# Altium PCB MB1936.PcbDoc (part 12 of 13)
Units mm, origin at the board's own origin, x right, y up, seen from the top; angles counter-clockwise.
Board outline 172 x 137 mm, 6 copper layers (Top Layer, Signal Layer 1, Signal Layer 2, Signal Layer 3, Signal Layer 4, Bottom Layer), stack 1.549 mm thick; 859 components, 672 nets, 3477 pads, 2222 vias.
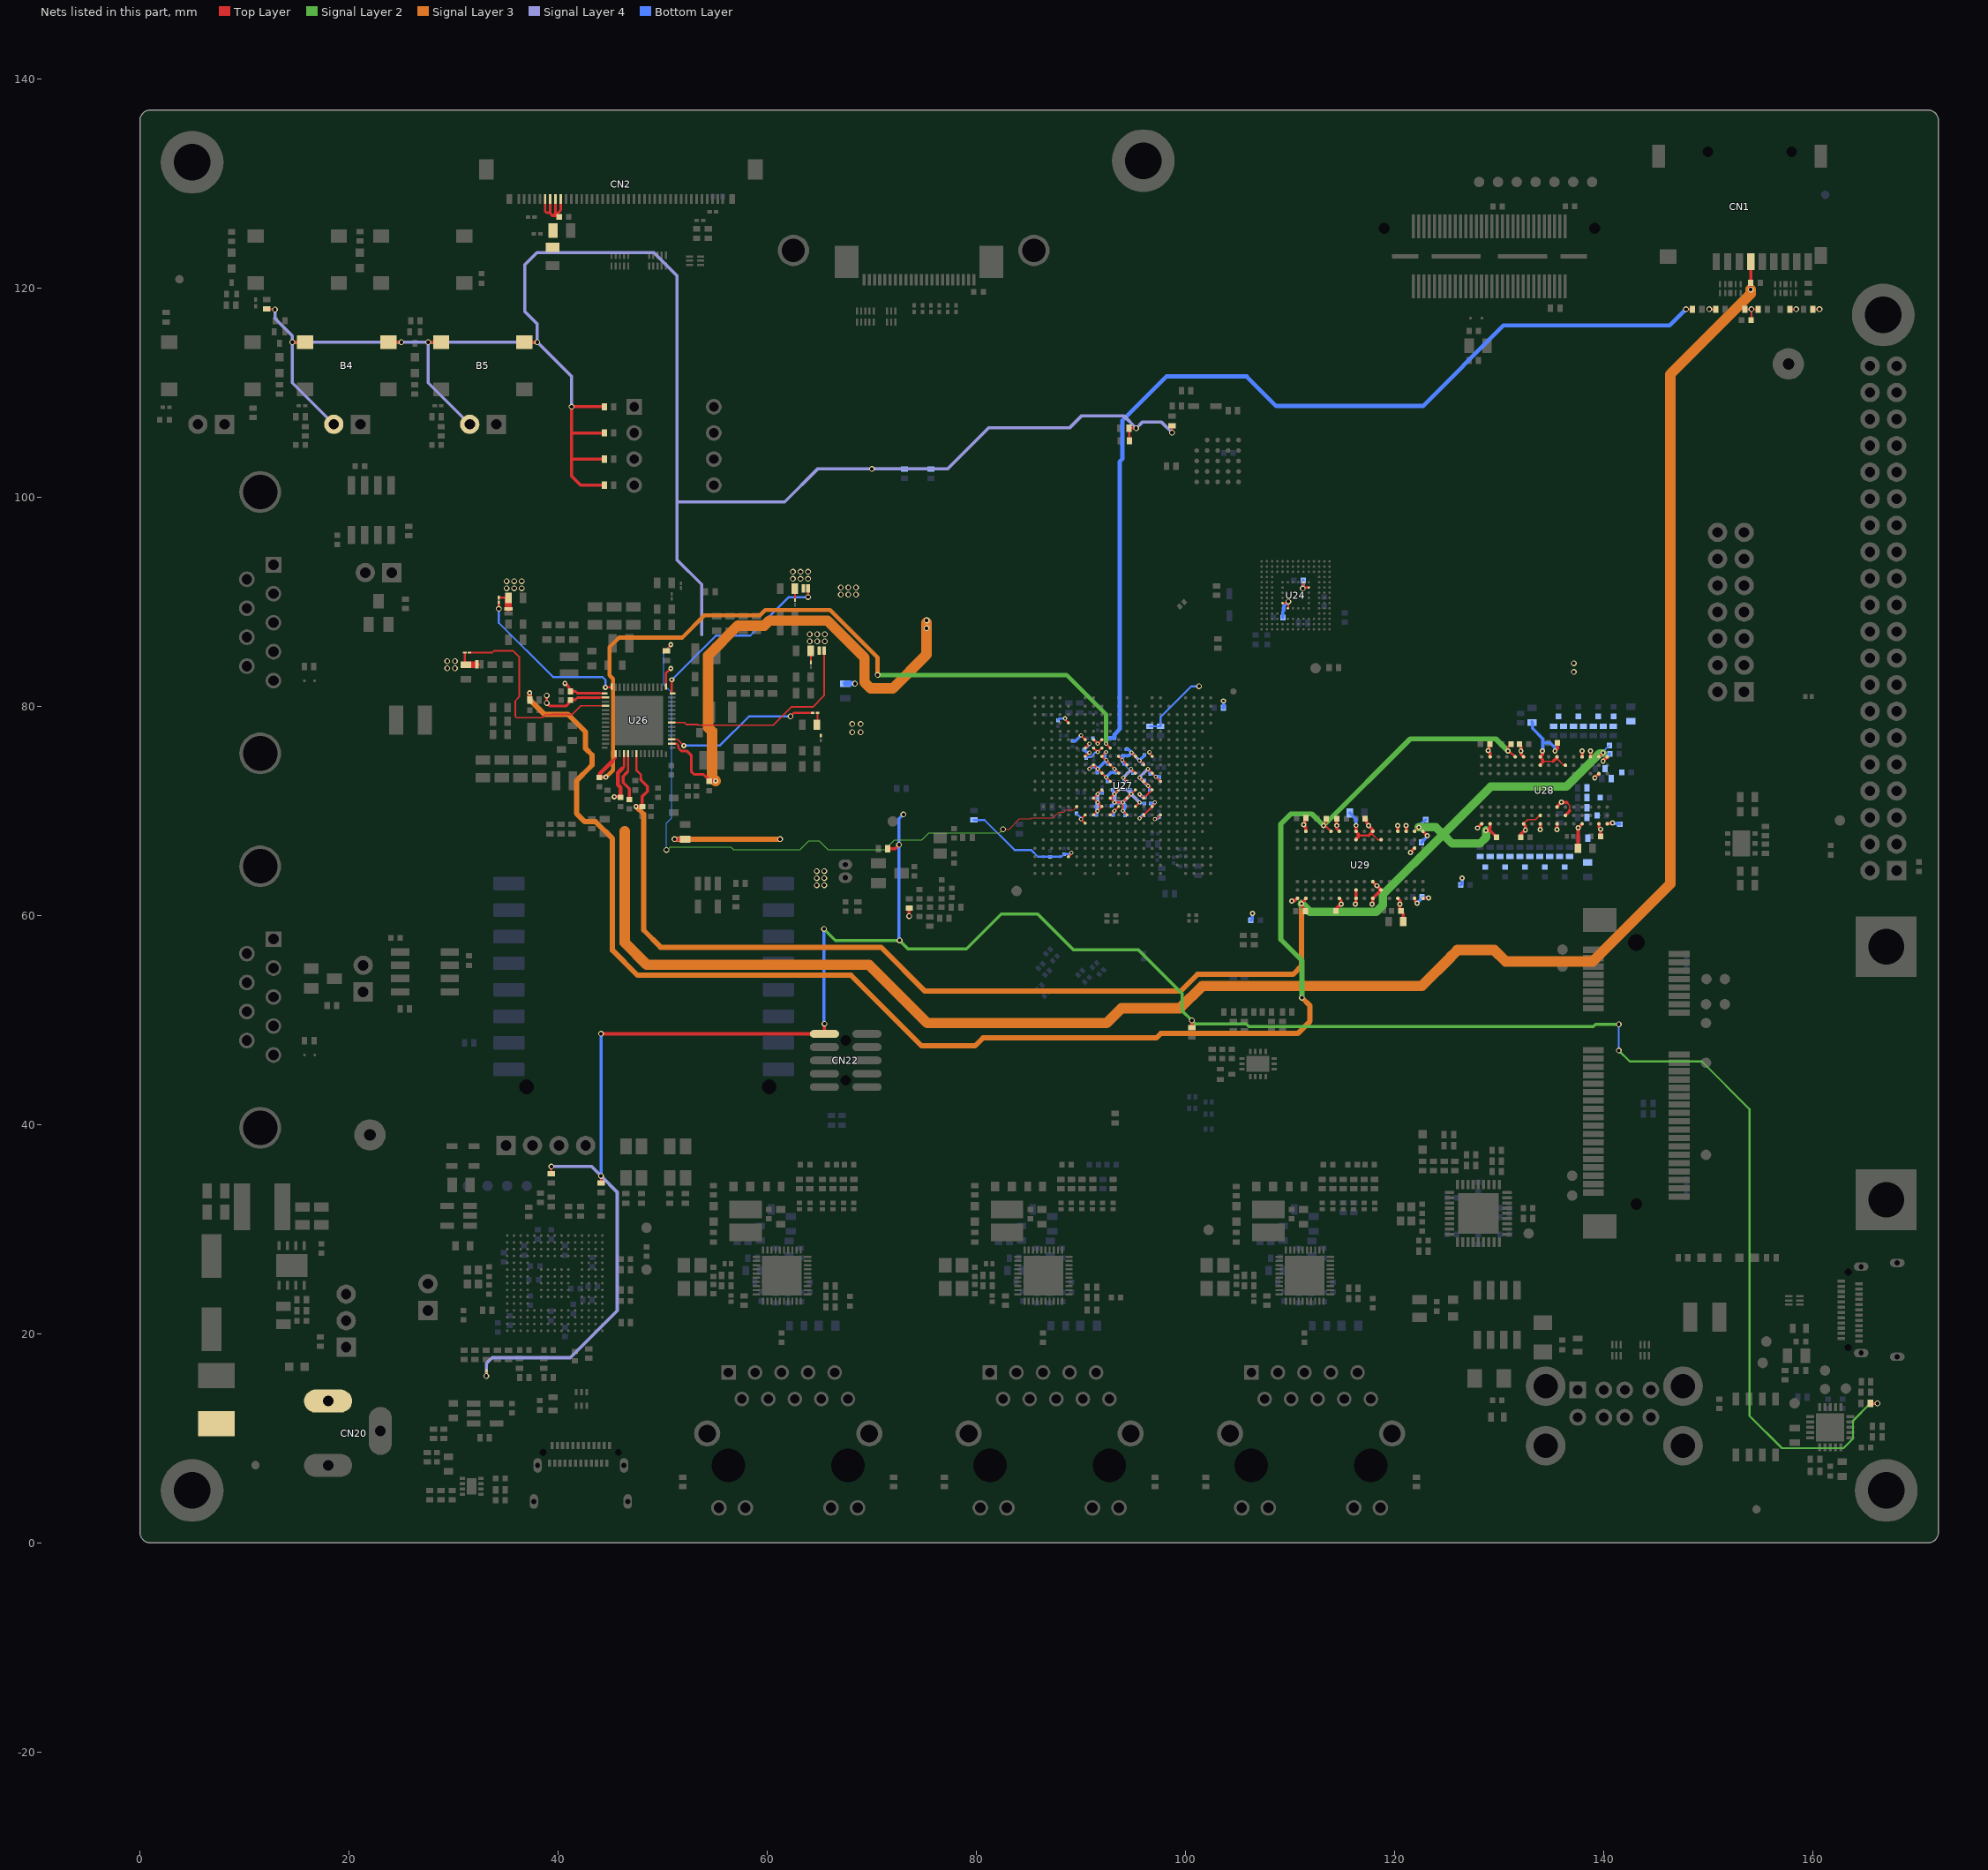
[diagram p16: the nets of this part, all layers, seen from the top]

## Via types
v1: diameter 0.55, hole 0.35, Top Layer to Bottom Layer, 1661 vias
v2: diameter 0.4, hole 0.2, Top Layer to Bottom Layer, tented both sides, 253 vias
v3: diameter 0.5, hole 0.2, Top Layer to Bottom Layer, 157 vias
v4: diameter 0.5, hole 0.25, Top Layer to Bottom Layer, 145 vias
v5: diameter 0.4, hole 0.2, Top Layer to Bottom Layer, 6 vias

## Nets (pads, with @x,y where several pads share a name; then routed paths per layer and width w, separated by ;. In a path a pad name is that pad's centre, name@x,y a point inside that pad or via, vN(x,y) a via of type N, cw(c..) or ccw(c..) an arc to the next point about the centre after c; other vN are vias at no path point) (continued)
VDD_DDR: C39.2 C48.2 C50.2 C51.2 C77.2 C79.2 C80.2 C82.2 C84.2 C85.2 C93.2 C94.2 C99.2 C188.2 C189.2 C202.2 C216.2 C217.2 C218.2 C224.2 C227.2 C230.1 C236.2 C237.2 C238.2 C243.2 C247.2 C261.2 C262.2 C264.2 LNK8.2 LNK9.2 R47.2 U26.43 U27.K15 U27.L14 U27.L16 U27.M15 U27.N14 U27.P15 U27.R14 U27.R16 U28.A1 U28.A9 U28.B3 U28.B9 U28.C1 U28.D1 U28.D9 U28.F2 U28.F8 U28.G1 U28.G7 U28.G9 U28.J1 U28.J2 U28.J8 U28.J9 U28.L1 U28.L9 U28.R1 U28.T9 U29.A1 U29.A9 U29.B3 U29.B9 U29.C1 U29.D1 U29.D9 U29.F2 U29.F8 U29.G1 U29.G7 U29.G9 U29.J1 U29.J2 U29.J8 U29.J9 U29.L1 U29.L9 U29.R1 U29.T9 | length 77.5
  Top Layer w0.09: U29.J8@116.269,62.399 U29.J8@116.269,62.424 ; 135.525,74.975 U28.G1@135.525,75.094
  Top Layer w0.1: U27.R16@97.575,69.6 U27.R16@97.6,69.6
  Top Layer w0.15: 117.718,67.815 117.757,67.815 117.797,67.775 117.845,67.775 118.389,67.232 118.694,67.232 U29.F2@118.7,67.225 ; U29.G1@117.9,67.998 U29.G1@117.9,68.025 ; U28.L9@132.325,68.75 132.325,68.775 132.7,69.15 133.475,69.15 U28.J8@133.936,69.611 ; 134.158,74.728 135.167,74.728 ; 135.525,74.975 136.15,74.35 U28.F2@136.325,74.35 ; 136.45,70.8 136.725,70.525 136.725,70.05
  Top Layer w0.2: LNK8.2@31.075,85.125 31.075,84.077 R47.2@31.175,83.977 ; v2(95.6,69.275) 95.675,69.275 U27.P15@96.8,70.4 97.05,70.65 v2(97.05,70.8) ; v2(95.6,73.15) 95.65,73.15 U27.L14@96,72.8 v2(96.42,72.379) ; v2@95.625,71.575 U27.N14@96,71.2 U27.M15@96.8,72 v2@96.421,72.379 ; v2(96.4,74) U27.K15@96.8,73.6 v2(97.15,73.25) ; v2(97.05,69.2) 97.2,69.2 U27.R16@97.6,69.6 ; v2@97.125,73.275 v2(97.15,73.25) ; U27.L16@97.6,72.8 v2(97.15,73.25) ; 116.526,67.625 117.535,67.625 ; U29.B9@121.9,61.625 121.906,61.619 121.906,61.394 v4(122.15,61.15) ; U29.A9@122.7,61.625 122.725,61.65 123.225,61.65 v4(123.25,61.675)
  Top Layer w0.21: 43.975,81.227 U26.43@44.53,81.227
  Top Layer w0.25: 40.895,81.952 40.899,81.952 41.045,81.806 41.045,81.512 C39.2@41.155,81.402 ; C39.2@41.205,81.402 41.675,81.402 41.85,81.227 43.975,81.227
  Top Layer w0.3: v3@40.644,82.203 40.895,81.952 ; v4@110.105,61.41 v4(110.144,61.372) 110.182,61.41 110.459,61.41 110.673,61.625 U29.T9@110.7,61.625 ; U29.R1@111.5,68.025 111.481,68.044 111.481,68.415 111.3,68.596 v4(111.3,68.65) 111.3,68.704 111.42,68.824 111.42,69.195 C77.2@111.525,69.3 ; C94.2@114.356,60.385 C94.2@114.394,60.422 ; C79.2@114.45,69.197 v4(114.45,68.6) 114.45,68.3 114.7,68.05 U29.L1@114.7,68.025 ; C94.2@114.468,60.697 114.846,61.075 v4(114.9,61.075) 114.862,61.113 114.862,61.436 114.7,61.598 U29.L9@114.7,61.625 ; v4(116.25,61.075) 116.3,61.125 U29.J9@116.3,61.625 U29.J8@116.3,62.425 ; U29.J2@116.3,67.225 116.32,67.244 116.32,67.317 116.526,67.524 116.526,67.625 116.526,67.772 116.3,67.998 U29.J1@116.3,68.025 v4(116.3,68.6) ; C80.2@117.325,69.25 117.325,68.857 117.4,68.782 117.4,68.729 117.5,68.629 v4(117.5,68.575) 117.5,68.55 117.881,68.169 117.881,68.044 U29.G1@117.9,68.025 ; 117.535,67.625 117.535,67.632 117.718,67.815 U29.G1@117.9,67.998 ; v4@117.896,61.08 117.9,61.084 U29.G9@117.9,61.625 U29.F8@118.7,62.425 118.688,62.425 118.3,62.813 v4(118.3,62.825) 117.913,63.213 117.9,63.213 U29.G7@117.9,63.225 ; U29.D9@120.3,61.625 120.5,61.425 v4(120.5,61.075) 120.47,61.045 120.47,60.53 120.575,60.425 120.825,60.175 C99.2@120.825,59.4 ; U29.D1@120.3,68.025 v4(120.3,68.575) ; U29.C1@121.1,68.025 v4(121.1,68.575) ; v4(121.5,66.025) U29.B3@121.9,66.425 ; U29.A1@122.7,68.025 v4(123.1,67.625) ; v4(127.927,68.35) 128.305,68.728 U28.T9@128.332,68.728 ; C51.2@129.052,76.298 129.052,75.927 128.932,75.807 128.932,75.699 129.113,75.518 U28.R1@129.113,75.147 ; C50.2@131.925,76.325 131.925,76.3 132.082,76.143 132.082,75.703 132.082,75.403 132.332,75.153 U28.L1@132.332,75.128 ; C84.2@132.025,67.425 C84.2@132.05,67.45 132.1,67.499 132.1,67.8 132.478,68.178 132.497,68.178 v4@132.5,68.175 ; U28.L9@132.332,68.701 132.5,68.533 v4@132.5,68.175 ; v4(132.5,68.15) v4@132.5,68.175 ; v4(133.9,68.2) 133.925,68.225 U28.J9@133.925,68.75 ; U28.J1@133.925,75.15 134.125,75.35 v4(134.125,75.7) ; U28.J2@133.932,74.328 133.951,74.347 133.951,74.42 134.158,74.627 134.158,74.728 134.158,74.875 U28.J1@133.932,75.101 ; 135.167,74.728 135.167,74.735 U28.G1@135.525,75.094 ; v4(135.325,75.7) 135.575,75.95 C48.2@135.575,76.375 ; v4(135.5,68.2) 135.525,68.225 U28.G9@135.525,68.75 ; U28.G7@135.525,70.35 135.525,70.4 v4(135.925,70.8) 136.45,70.8 ; U28.F8@136.325,69.55 136.725,69.95 136.725,70.05 ; C85.2@137.525,66.425 137.542,66.442 137.542,68.367 v4(137.55,68.375) 137.903,68.728 U28.D9@137.932,68.728 ; U28.D1@137.932,75.128 v4@137.932,75.678 ; U28.C1@138.732,75.128 v4@138.732,75.678 ; v4(139.125,73.15) U28.B3@139.525,73.55 ; U28.B9@139.525,68.75 139.535,68.74 139.535,68.445 139.7,68.279 v4(139.7,68.225) 139.688,68.213 139.688,67.563 C82.2@139.675,67.55 ; v4(139.925,74.75) U28.A1@140.325,75.15 ; U28.A9@140.325,68.75 140.335,68.76 140.73,68.76 140.796,68.825 v4(140.85,68.825)
  Top Layer w0.64: R47.2@31.175,83.977 LNK9.2@32.173,83.977
  Signal Layer 4 w0.3: v2(95.6,73.15) 96.356,72.394 96.406,72.394 v2@96.425,72.375 ; v2@95.716,73.179 95.716,73.316 v2(96.4,74)
  Bottom Layer w0.09: C202.2@140.55,75.425 C202.2@140.575,75.4
  Bottom Layer w0.2: v2(96.4,74) 96.4,73.946 96.549,73.796 96.549,73.599 C216.2@96.624,73.524 ; C216.2@96.631,73.524 96.704,73.452 96.933,73.452 97.135,73.25 v2(97.15,73.25) ; v2@97.125,73.275 v2(97.15,73.25) ; v2@97.15,73.23 v2(97.15,73.25)
  Bottom Layer w0.3: v2@95.6,69.229 v2(95.6,69.275) 95.875,69.55 95.95,69.55 C243.2@95.975,69.575 ; v2(95.6,71.575) 95.9,71.275 C227.2@96.1,71.275 ; v2(95.6,73.15) 95.627,73.15 95.863,72.914 96.035,72.914 96.074,72.874 96.099,72.85 96.099,72.7 v2(96.42,72.379) ; v2@96.425,72.375 96.425,72.347 96.549,72.223 96.549,71.999 C224.2@96.574,71.974 ; C230.1@96.675,70.7 96.7,70.725 96.948,70.725 97.023,70.8 v2(97.05,70.8) ; v2(97.05,69.2) 97.069,69.219 97.269,69.219 C237.2@97.45,69.4 ; v2@97.125,73.275 97.425,73.275 C217.2@97.5,73.2 ; C189.2@103.62,79.846 103.625,79.851 v4(103.625,80.5) ; C264.2@106.25,59.525 106.4,59.675 v4(106.4,60.175) ; C236.2@115.7,69.8 116.088,69.412 ; 116.125,69.375 116.3,69.2 v4(116.3,68.6) ; v4@122.075,61.1 122.65,61.675 v4(123.25,61.675) ; C247.2@122.575,66.975 123.1,67.5 v4(123.1,67.625) ; C261.2@126.3,62.9 126.45,63.05 v4(126.45,63.55) ; C188.2@133.125,78.5 C188.2@133.125,78.425 133.166,78.384 133.166,77.873 134.166,76.873 134.166,76.487 ; v4(134.125,75.7) 134.166,75.741 134.166,76.487 ; v4(135.325,75.7) 135.325,76.025 134.864,76.487 134.166,76.487 ; v4(139.925,74.75) 139.925,74.8 140.55,75.425 C202.2@140.438,75.313 ; v4@140.875,68.775 141.475,68.775 C238.2@141.525,68.725
  other v1: 29.4,83.625 30.125,83.625 29.4,84.3 30.125,84.3
  other v3: 40.65,82.175
  other v4: 117.85,61.075 137.925,75.7 138.725,75.7 132.075,75.725 128.925,75.75
VDD_DDR_FB: LNK8.1 U26.46 | length 20.1
  Top Layer w0.15: LNK8.1@31.525,85.125 33.7,85.125 33.875,85.3 35.687,85.3 35.871,85.116 36.275,84.712 36.275,80.875 35.9,80.5 35.9,79.017 36.017,78.9 38.467,78.9 38.767,79.2 39.437,79.2 39.439,79.202 41.327,79.202 42.152,80.027 U26.46@44.53,80.027
VDD_EMMC: C65.1 C177.2 C180.2 U24.E6 U24.F5 U24.J10 U24.K9 U26.16 | length 54.6
  Top Layer w0.2: U24.E6@109.275,89.85 109.58,89.85 109.73,90 v1(109.825,90) ; U24.F5@109.775,89.35 109.775,89.358 109.825,89.408 v1@109.825,89.85 ; v1(111.2,91.25) v1@111.275,91.325 ; U24.J10@111.275,91.85 111.275,91.42 111.267,91.412 111.267,91.333 v1@111.275,91.325 ; U24.K9@111.775,91.35 111.395,91.35 111.362,91.317 111.283,91.317 v1@111.275,91.325
  Top Layer w0.21: U26.16@50.87,76.427 51.3,76.427 51.488,76.24 51.488,76.015 51.634,75.868
  Top Layer w0.25: 51.632,75.865 51.798,75.699 52.328,75.699 52.725,75.302 52.725,73.752 53,73.477 53.895,73.477 54.45,72.922 C65.1@54.45,72.852
  Top Layer w0.3: C65.1@54.45,72.852 v3(55.06,72.852)
  Signal Layer 3 w1: v3(55.06,72.852) 54.705,73.207 54.705,77.595 54.35,77.95 54.35,84.85 57.206,87.706 59.719,87.706 60.188,88.175 65.75,88.175 69.3,84.625 69.3,82.286 69.886,81.7 72,81.7 75.225,84.925 v1(75.225,87.45) v1@75.225,88
  Bottom Layer w0.3: C180.2@109.3,88.475 109.3,89.049 109.4,89.149 109.4,89.575 v1(109.825,90) ; v1(111.2,91.25) 111.225,91.275 111.225,92 C177.2@111.25,92.025
  other v1: 75.225,88.2
VDD_SDCARD: C6.2 C72.1 CN1.4 U26.4 | length 188
  Top Layer w0.21: 46.125,74.027 46.3,74.202 U26.4@46.3,75.457
  Top Layer w0.3: v3(45.365,71.337) C72.1@45.975,71.337 ; v1(154.05,119.83) C6.2@154.05,120.48 CN1.4@154.05,122.5
  Top Layer w0.4: C72.1@45.975,71.337 45.975,72.22 45.71,72.485 45.71,73.612 46.125,74.027
  Signal Layer 3 w1: 46.375,68.025 46.375,57.375 48.475,55.275 69.725,55.275 75.3,49.7 92.45,49.7 93.875,51.125 99.475,51.125 101.6,53.25 122.6,53.25 125.4,56.05 125.4,56.089 125.986,56.675 129.525,56.675 130.6,55.6 138.95,55.6 146.35,63 146.35,111.725 154.05,119.425 v1(154.05,119.83)
VDD_XXXX: C73.1 U26.5 | length 4.6
  Top Layer w0.21: 46.578,73.655 46.7,73.777 U26.5@46.7,75.457
  Top Layer w0.3: 46.578,73.655 46.21,73.287 46.21,72.692 46.8,72.102 46.8,71.337
VDDA1V8_AON: C234.2 R58.2 R70.1 U27.R7 U27.T7 | length 13.7
  Top Layer w0.2: v2(90,69.2) U27.R7@90.4,69.6 ; v2(90,69.2) U27.T7@90.4,68.8
  Top Layer w0.3: v1(51.125,67.275) R58.2@52.15,67.275 ; v1(73.575,59.925) R70.1@73.575,60.675
  Signal Layer 3 w0.5: v1(51.125,67.275) v1(61.225,67.275)
  Bottom Layer w0.2: C234.2@89.575,69.7 89.625,69.7 89.962,69.364 89.962,69.238 v2(90,69.2)
VDDCORE: C192.2 C197.2 C201.2 C204.1 C207.2 C210.2 C213.2 C214.2 C219.1 LNK2.2 LNK5.1 R36.2 R249.1 U27.D5 U27.F7 U27.G7 U27.H7 U27.H9 U27.J8 U27.J10 U27.K9 U27.K11 U27.L10 | length 18.9
  Top Layer w0.2: LNK5.1@62.65,90.15 62.65,91.232 R36.2@62.63,91.252 R36.2@62.653,91.275 ; v2(88.475,78.825) 88.475,78.725 U27.D5@88.8,78.4 ; v2(90,77.2) U27.F7@90.4,76.8 U27.F7@90.425,76.8 ; U27.H7@90.4,75.2 90.425,75.2 90.775,75.55 v2(90.8,75.55) ; U27.G7@90.4,76 v2(90.8,76.4) ; v2(90.8,74) U27.J8@91.2,74.4 v2(91.6,74) v2(92.4,73.2) U27.L10@92.8,72.8 ; v2(92.4,75.6) U27.H9@92,75.2 v2@92.425,74.775 ; v2(92.425,74.85) v2@92.425,74.775 ; U27.K11@93.6,73.6 v2(93.2,74) U27.J10@92.8,74.4 v2@92.425,74.775
  Bottom Layer w0.2: C192.2@87.8,78.7 87.9,78.8 88.038,78.8 v2@88.4,78.8
  Bottom Layer w0.3: C197.2@89.2,76.675 89.475,76.675 v2(90,77.2) ; v2(90.8,74) 91,74.2 91.4,74.2 v2(91.6,74) ; v2(90.8,75.55) 90.576,75.55 C201.2@90.3,75.825 90.8,76.325 v2(90.8,76.4) ; C214.2@91.55,73.65 91.55,73.95 v2(91.6,74) ; v2(92.4,75.6) 92.275,75.475 C204.1@92.275,75.25 92.275,75 v2(92.425,74.85) ; C219.1@92.55,72.825 92.55,73.05 v2(92.4,73.2) 92.85,73.65 C213.2@93.326,73.65 93.325,73.875 v2(93.2,74) ; C210.2@92.551,74.475 92.55,74.725 v2(92.425,74.85) ; v2(91.6,74) 92.425,74.825 v2(92.425,74.85)
  Bottom Layer w0.5: R249.1@67.45,82.15 v1(68.375,82.15)
  other v1: 62.45,92.175 63.175,92.175 63.9,92.175 62.45,92.85 63.175,92.85 63.9,92.85
VDDCORE_FB: LNK2.1 U26.28 | length 18.5
  Top Layer w0.2: U26.28@50.87,81.227 v3(50.87,82.527) ; v1(63.9,90.425) LNK2.1@63.9,91.275
  Bottom Layer w0.2: v3(50.87,82.527) 55.093,86.75 58.375,86.75 62.05,90.425 v1(63.9,90.425)
VDDCPU: C199.2 C200.1 C203.2 C208.2 C209.2 C215.1 C220.2 LNK4.1 LNK6.1 R39.2 U27.H11 U27.H13 U27.H15 U27.J12 U27.J14 U27.K13 U27.L12 | length 13.4
  Top Layer w0.2: LNK4.1@34.325,90.375 35.222,90.375 R39.2@35.245,90.352 ; U27.H11@93.6,75.2 v2(93.945,74.855) U27.J12@94.4,74.4 ; v2(94.045,73.155) U27.L12@94.4,72.8 ; v2(94.775,74.005) 95.18,73.6 U27.K13@95.2,73.6 ; v2(94.845,75.555) U27.H13@95.2,75.2 ; v2(95.595,74.805) U27.J14@96,74.4 ; v2(96.54,75.591) 96.578,75.553 96.578,75.449 96.8,75.227 U27.H15@96.8,75.2
  Top Layer w0.64: LNK6.1@35.225,89.354 R39.2@35.225,90.352
  Signal Layer 4 w0.3: v2(94.045,73.155) 94.756,73.866 94.756,73.986 v2(94.775,74.005) ; v2(94.845,75.555) v2(95.595,74.805)
  Bottom Layer w0.1: C208.2@94.15,74.48 94.15,74.379 94.524,74.005 v2(94.775,74.005)
  Bottom Layer w0.2: v2(94.045,73.155) 94.045,72.855 C220.2@94.125,72.775 ; v2@94.775,73.978 v2(94.775,74.005) ; C215.1@94.95,73.625 94.95,73.803 ; v2(95.595,74.805) 95.633,74.767 95.633,74.692 C209.2@95.875,74.45
  Bottom Layer w0.3: C208.2@94.15,74.48 93.945,74.685 v2(93.945,74.855) 93.945,75.17 C203.2@94.025,75.25 94.548,75.25 v2@94.853,75.555 ; C199.2@94.325,75.875 94.525,75.875 v2(94.845,75.555) ; v2@94.775,73.978 94.95,73.803 ; v2(95.595,74.805) C200.1@96.095,75.305
  other v1: 67.025,90.666 67.75,90.666 68.475,90.666 35.065,91.273 35.79,91.273 36.515,91.273 67.025,91.341 67.75,91.341 68.475,91.341 35.065,91.948 35.79,91.948 36.515,91.948
VDDCPU_FB: LNK4.2 U26.42 | length 15.7
  Top Layer w0.2: v1(34.325,89.3) LNK4.2@34.325,89.925 ; v3(44.525,81.802) U26.42@45.095,81.802
  Bottom Layer w0.2: v1(34.325,89.3) 34.325,87.975 39.51,82.79 44.235,82.79 44.525,82.5 v3(44.525,81.802)
VDDGPU: C222.2 C223.2 C229.1 C231.2 C232.2 C242.2 LNK7.2 LNK10.1 R45.2 U27.M11 U27.M13 U27.N10 U27.N12 U27.P13 U27.R12 | length 19.9
  Top Layer w0.2: LNK10.1@64.175,84.175 R45.2@64.175,85.257 ; U27.M11@93.6,72 v2(93.2,71.6) U27.N10@92.8,71.2 v2(93.195,70.805) 93.197,70.803 93.997,70.803 v2(94,70.8) ; U27.R12@94.4,69.6 v2(94,70) v2(94,70.8) ; U27.P13@95.2,70.4 v2(95.6,70.8) ; U27.M13@95.2,72 v2(94.8,71.6) v2(94,70.8)
  Signal Layer 4 w0.2: v2(94,70) v2(94,70.8)
  Signal Layer 4 w0.3: v2(93.2,71.6) 93.675,72.075 94.325,72.075 v2(94.8,71.6) ; v2(94,70.8) v2(94.8,71.6) ; v2(95.6,70.8) v2(94.8,71.6)
  Signal Layer 4 w0.4: v2(93.2,71.6) 93.2,70.8 v2(94,70.8)
  Bottom Layer w0.2: C223.2@93.025,72 93.025,71.775 v2(93.2,71.6) 93.197,71.598 93.197,70.808 v2(93.195,70.805) 93.197,70.803 93.997,70.803 v2(94,70.8) ; v2(95.6,70.8) 95.695,70.705 C229.1@96.075,70.705
  Bottom Layer w0.3: C231.2@92.95,70.48 93.176,70.706 93.176,70.786 v2(93.195,70.805) ; v2(94,70.8) 94.175,70.625 C232.2@94.175,70.425 94.175,70.175 v2(94,70) 94.2,69.8 C242.2@94.2,69.575 ; C222.2@94.675,72 94.8,71.875 v2(94.8,71.6) v2(95.6,70.8)
  other v1: 64.725,62.875 65.45,62.875 64.725,63.55 65.45,63.55 64.725,64.225 65.45,64.225 64.05,86.2 64.775,86.2 65.5,86.2 64.05,86.875 64.775,86.875 65.5,86.875
VDDGPU_FB: LNK7.1 U26.21 | length 20.2
  Top Layer w0.15: U26.21@50.75,78.427 52.083,78.427 52.26,78.25 53.34,78.25 53.413,78.177 60.552,78.177 62.3,79.925 64.35,79.925 65.425,81 LNK7.1@65.425,85.3
VDDIO: B4.1 B4.2 B5.1 B5.2 C196.2 C205.2 C221.2 C228.2 C233.1 C240.2 C241.1 CN7.2 CN8.2 CN22.1 LNK11.2 LNK12.2 LNK13.1 R7.2 R27.2 R31.2 R32.2 R53.2 R67.2 R68.2 R71.2 R76.2 R79.2 R91.2 R107.2 R125.2 R223.2 R245.2 R246.2 R260.2 R261.2 U26.29 U27.F8 U27.F9 U27.G8 U27.G9 U27.M9 U27.N8 U27.P9 U27.P11 U27.R8 U27.R10 | length 464.8
  Top Layer w0.2: R7.2@12.123,117.975 12.148,117.95 12.893,117.95 v1(12.918,117.925) ; v1(33.125,15.95) LNK13.1@33.125,16.43 ; R107.2@39.35,35.3 v1(39.35,35.975) ; R125.2@44.1,34.4 v1(44.1,35.075) ; U26.29@50.3,81.872 50.3,83.125 v3(50.775,83.6) ; R53.2@64.755,78.227 64.8,78.272 LNK11.2@64.8,79.375 ; U27.R8@91.2,69.6 v2(91.575,69.975) U27.P9@92,70.4 v2(91.6,70.8) U27.N8@91.2,71.2 v2(91.6,71.6) U27.M9@92,72 ; U27.G8@91.2,76 91.599,75.6 U27.G9@92,76 ; U27.F8@91.2,76.8 v2(91.6,76.4) U27.F9@92,76.8 ; U27.R10@92.8,69.6 v2(93.2,70) U27.P11@93.6,70.4 ; R32.2@94.63,105.375 94.605,105.4 R31.2@94.605,106.575 v1(95.28,106.575) ; v1(98.709,106.15) R27.2@98.709,106.825 ; R223.2@165.495,13.325 v1(166.17,13.325)
  Top Layer w0.3: v1(14.567,114.8) B4.1@15.812,114.8 ; B4.2@23.763,114.8 v1(25.007,114.8) ; v1(27.568,114.8) B5.1@28.813,114.8 ; B5.2@36.763,114.8 v1(38.008,114.8) ; v1@44.1,48.665 CN22.1@65.465,48.665 65.475,48.675 v1(65.475,49.625) ; R79.2@44.425,101.125 42.15,101.125 41.275,102 41.275,103.575 ; R76.2@44.425,103.625 41.325,103.625 41.275,103.575 ; R71.2@44.425,106.125 41.3,106.125 41.275,106.1 ; R68.2@44.425,108.625 v1(41.275,108.625) 41.275,106.1 ; R67.2@71.525,66.375 72.225,66.375 v1(72.6,66.75) ; R91.2@100.6,49.275 v1(100.6,49.95) ; 41.275,103.575 41.275,106.1
  Signal Layer 2 w0.2: v1(141.425,47.075) 142.475,46.025 149.375,46.025 153.925,41.475 153.925,12.154 157.029,9.05 162.92,9.05 163.825,9.955 163.825,11.672 165.478,13.325 v1(166.17,13.325)
  Signal Layer 2 w0.3: v1(65.425,58.7) 66.525,57.6 v1(72.65,57.6) 73.45,56.8 79.05,56.8 82.375,60.125 85.85,60.125 89.288,56.687 95.489,56.687 99.656,52.52 99.656,50.894 v1(100.6,49.95) 100.925,49.625 105.8,49.625 106.05,49.375 139,49.375 139.2,49.575 v1(141.425,49.575)
  Signal Layer 4 w0.3: v1(12.918,117.925) 12.918,117.057 14.567,115.408 v1(14.567,114.8) ; CN7.2@18.543,106.95 14.567,110.925 v1(14.567,114.8) ; CN8.2@31.543,106.95 27.568,110.925 v1(27.568,114.8) ; v1(33.125,15.95) 33.125,17.15 33.675,17.7 41.15,17.7 45.65,22.2 45.65,33.525 v1(44.1,35.075) 43.2,35.975 v1(39.35,35.975) ; v1(41.275,108.625) 41.275,111.533 v1(38.008,114.8) ; 53.725,86.825 53.725,91.625 51.35,94 51.35,99.525 ; v2(91.575,69.975) 91.6,70 v2(91.6,71.6) ; v1(98.709,106.15) 97.709,107.15 95.855,107.15 v1(95.28,106.575) 94.08,107.775 90.075,107.775 88.9,106.6 81.15,106.6 77.225,102.675 v1(70,102.675) 64.8,102.675 61.65,99.525 51.35,99.525 ; v1(14.567,114.8) v1(25.007,114.8) v1(27.568,114.8) ; v1(27.568,114.8) v1(38.008,114.8) ; v1(38.008,114.8) 38.008,116.542 36.825,117.725 36.825,122.225 37.975,123.375 49.15,123.375 51.35,121.175 51.35,99.525
  Bottom Layer w0.2: C205.2@90.5,75.05 90.575,75.125 90.667,75.125 90.692,75.15 90.931,75.15 90.946,75.165 90.981,75.165 91.2,75.384 91.2,75.419 91.342,75.561 91.561,75.561 v2(91.599,75.599) ; C196.2@91.125,76.925 91.6,76.45 v2(91.6,76.4) ; R261.2@96.575,78.075 R260.2@97.6,78.075 97.6,78.95 100.55,81.9 v1(101.29,81.9) ; v1(141.425,47.075) v1(141.425,49.575)
  Bottom Layer w0.3: v1(44.1,35.075) v1(44.1,48.675) ; v1(65.425,58.7) 65.425,49.743 65.475,49.693 v1(65.475,49.625) ; v1(70,102.675) R246.2@73.109,102.675 R245.2@75.649,102.675 ; v1(72.65,57.6) 72.65,57.668 72.6,57.718 v1(72.6,66.75) 72.6,69.225 v1(73.025,69.65) ; C241.1@91.475,69.6 91.475,69.875 v2(91.575,69.975) 91.475,70.075 91.475,70.675 v2(91.6,70.8) 91.475,70.925 91.475,71.475 91.725,71.725 C221.2@92.025,71.725 ; C240.2@93.075,69.6 93.075,69.875 v2(93.2,70) v2@93.225,70
  other v1: 68.125,77.5 68.925,77.5 68.125,78.3 68.925,78.3
VDDIO_FB: LNK11.1 U26.17 | length 15
  Top Layer w0.15: U26.17@50.87,76.827 51.4,76.827 52.003,76.224 v3(52.015,76.224)
  Top Layer w0.2: v1(62.225,79.025) 62.575,79.375 LNK11.1@64.35,79.375
  Bottom Layer w0.2: v3(52.015,76.224) 55.449,76.224 58.25,79.025 v1(62.225,79.025)
VDDIO_SDCARD: C8.2 C63.1 C195.2 R10.2 R11.2 R12.2 R13.2 R14.2 R15.2 U26.2 U27.G10 | length 171.1
  Top Layer w0.2: v2(92.4,76.4) U27.G10@92.8,76 ; v1(147.855,117.95) R10.2@148.475,117.95 ; v1(150.08,117.95) R11.2@150.7,117.95 ; R12.2@153.5,117.95 v1(154.12,117.95) ; C8.2@154.075,116.925 154.12,116.97 v1(154.12,117.95) ; R13.2@154.74,117.95 v1(154.12,117.95) ; R14.2@157.775,117.95 v1(158.395,117.95) ; R15.2@160,117.95 v1(160.62,117.95)
  Top Layer w0.21: 45.159,74.7 45.5,75.041 U26.2@45.5,75.457
  Top Layer w0.3: C63.1@43.95,73.207 v3(44.56,73.207)
  Top Layer w0.4: C63.1@43.95,73.207 43.99,73.247 43.99,73.531 45.159,74.7
  Signal Layer 2 w0.4: v1(70.55,82.975) 88.625,82.975 92.4,79.2 v2(92.4,76.4)
  Signal Layer 3 w0.4: v3(44.56,73.207) 45.25,73.897 45.25,82.6 44.9,82.95 44.9,85.65 45.8,86.55 51.85,86.55 53.975,88.675 59.301,88.675 59.813,89.188 65.987,89.188 70.55,84.625 v1(70.55,82.975)
  Bottom Layer w0.4: v2(92.4,76.4) 92.4,76.715 92.635,76.95 C195.2@93.201,76.95 93.201,77.294 93.7,77.793 93.7,103.366 93.95,103.616 93.95,107.304 98.171,111.525 102.45,111.525 105.85,111.525 108.675,108.7 122.7,108.7 130.4,116.4 146.305,116.4 v1(147.855,117.95)
VIN_JACK: CN20.1 F1.1
VLED: C3.2 C4.2 CN2.32 CN2.33 CN2.34 CN2.35 R5.1 | length 7.3
  Top Layer w0.25: CN2.35@38.75,128.5 38.75,127.321 38.896,127.175 39.175,127.175 39.25,127.1 ; CN2.34@39.25,128.5 39.25,127.1 ; CN2.33@39.75,128.5 39.75,127.15 39.475,126.875 ; CN2.32@40.25,128.5 40.25,127.425 39.8,126.975 39.7,126.875 39.475,126.875 ; 39.25,127.1 39.475,126.875
VPP_DDR: C74.1 C83.2 C95.2 C198.2 C245.2 U26.7 U28.B1 U28.R9 U29.B1 U29.R9 | length 141.4
  Top Layer w0.09: U29.B1@121.894,68.024 U29.B1@121.971,68.024 ; U28.B1@139.526,75.127 U28.B1@139.602,75.127
  Top Layer w0.15: U29.B1@121.9,68.025 v4(122.3,68.425)
  Top Layer w0.21: U26.7@47.5,75.457 47.5,73.852 47.915,73.437 47.915,73.08
  Top Layer w0.3: v3(47.44,70.407) C74.1@48.05,70.407 ; 47.915,73.08 47.915,72.945 48.535,72.325 48.535,71.862 48.05,71.377 C74.1@48.05,70.557 ; C95.2@111.45,60.4 111.475,60.425 111.475,60.45 111.1,60.825 v4(111.1,61.1) 111.1,61.175 111.5,61.575 U29.R9@111.5,61.625 ; v4(128.725,68.125) v4@128.882,68.125 ; U28.R9@129.125,68.75 129.125,68.368 128.979,68.222 v4@128.882,68.125 ; C83.2@129.75,67.45 129.075,68.125 v4@128.882,68.125 ; U28.B1@139.532,75.128 v4@139.932,75.528
  Signal Layer 2 w0.8: v4@111.087,61.087 v4(111.1,61.1) 111.875,60.325 118.225,60.325 118.854,60.954 118.854,61.976 124.62,67.743 ; v4(122.3,68.425) 123.938,68.425 124.62,67.743 ; v4(128.725,68.125) 128.725,67.45 128.152,66.876 125.487,66.876 124.62,67.743 ; v4@139.875,75.5 139.615,75.5 136.415,72.3 129.178,72.3 124.62,67.743
  Signal Layer 3 w0.5: v3(47.44,70.407) 48.175,69.672 48.175,58.575 49.8,56.95 70.875,56.95 75.075,52.75 99.525,52.75 101.128,54.353 110.28,54.353 111.1,55.173 111.1,59.475 v4(111.1,61.1)
  Bottom Layer w0.09: v4(139.925,75.55) v4@139.925,75.65 ; C198.2@140.5,76.225 C198.2@140.55,76.225
  Bottom Layer w0.15: v4@139.925,75.65 C198.2@140.5,76.225
  Bottom Layer w0.3: v4(122.3,68.425) 122.339,68.463 122.339,68.538 122.95,69.15 C245.2@122.975,69.15
VREF+: C248.2 C250.2 R269.2 U27.Y5 | length 11.4
  Top Layer w0.2: U27.Y5@88.8,65.6 89.037,65.837 89.037,65.942 v2(89.076,65.981)
  Bottom Layer w0.2: R269.2@79.763,69.113 80.775,69.113 83.638,66.25 85.229,66.25 85.879,65.6 C250.2@87.025,65.6 88.125,65.6 C248.2@88.375,65.85 88.904,65.85 89.035,65.981 v2(89.076,65.981)
VREF_DDR: C49.2 C78.2 R52.2 U28.M1 U29.M1 | length 152.8
  Top Layer w0.2: C78.2@113.45,69.25 113.45,68.825 113.275,68.65 U29.M1@113.9,68.025 ; v4(130.825,75.725) 130.927,75.725 131.502,75.15 U28.M1@131.525,75.15 ; v4@130.836,75.84 130.836,76.085 C49.2@131.125,76.375
  Top Layer w0.3: R52.2@37.275,80.575 v3@37.275,81.185
  Signal Layer 2 w0.5: v1(111.125,52.125) 111.125,55.675 109.1,57.7 109.1,68.725 110.075,69.7 112.075,69.7 v4(113.2,68.575) 121.5,76.875 129.675,76.875 v4(130.825,75.725)
  Signal Layer 3 w0.5: v3(37.275,81.275) 37.275,80.625 38.675,79.225 40.925,79.225 42.625,77.525 42.625,75.95 43.248,75.327 43.248,74.364 43.075,74.191 41.75,72.866 41.75,69.75 42.55,68.95 43.575,68.95 45.2,67.325 45.2,56.65 47.575,54.275 53.875,54.275 68,54.275 74.75,47.525 79.875,47.525 80.625,48.275 97.2,48.275 97.625,48.7 110.725,48.7 111.9,49.875 111.9,51.35 v1(111.125,52.125)
VTT_DDR: C40.2 C183.2 C184.2 C185.2 C186.2 C187.2 C211.2 C226.2 C239.2 C254.2 C255.2 C256.2 C257.2 C258.2 C259.2 R253.2 R254.2 R255.2 R256.2 R257.2 R258.2 R259.2 R263.2 R264.2 R265.2 R266.2 R268.2 R271.2 R273.2 R275.2 R276.2 R277.2 R278.2 R279.2 R280.2 R281.2 R282.2 R283.2 R284.2 U26.44 | length 7
  Top Layer w0.21: 43.975,80.827 U26.44@44.53,80.827
  Top Layer w0.25: v1(38.9,81.025) v1(38.9,81.025) v1(38.902,80.3) ; v1@38.925,80.3 v1(38.902,80.3) ; C40.2@41.205,80.577 41.135,80.577 41.02,80.462 41.02,80.272 40.775,80.027 39.175,80.027 v1(38.902,80.3) ; C40.2@41.21,80.462 41.365,80.617 41.64,80.617 41.85,80.827 43.975,80.827
  other v1: 137.125,83.275 137.125,84.1
WAKEUPn: R46.1 U27.P6 | length 63.1
  Top Layer w0.09: v1(82.55,68.225) 83.125,68.225 84.12,69.22 84.698,69.22 84.703,69.215 85.189,69.215 85.289,69.315 87.318,69.315 87.6,69.597 87.6,69.603 87.882,69.885 88.356,69.885 88.546,70.075 89.275,70.075 U27.P6@89.6,70.4
  Top Layer w0.15: R46.1@50.35,85.275 50.512,85.437 50.512,85.612 v3(50.775,85.875)
  Signal Layer 2 w0.1: v1(50.35,66.25) 50.418,66.25 50.718,66.55 56.525,66.55 56.775,66.3 63.142,66.3 63.967,67.125 64.958,67.125 65.783,66.3 71.275,66.3 72.175,67.2 74.794,67.2 75.469,67.875 82.2,67.875 v1(82.55,68.225)
  Bottom Layer w0.1: v1(50.35,66.25) 50.35,68.825 50.85,69.325 50.85,81.3 50.1,82.05 50.1,85.2 v3(50.775,85.875)
pads on no net: CART-1.1 CN1.13 CN1.NPTH1 CN1.NPTH2 CN2.20 CN2.21 CN2.22 CN2.23 CN2.24 CN2.25 CN2.26 CN2.27 CN2.28 CN2.29 CN3.2 CN3.20 CN3.22 CN3.24 CN3.25 CN3.26 CN3.28 CN3.30 CN3.31 CN3.33 CN3.34 CN3.38 CN3.41 CN3.42 CN3.43 CN3.45 CN3.51 CN3.55 CN3.59 CN3.65 CN3.66 CN9.1 CN9.4 CN9.8 CN11.1 CN11.4 CN11.8 CN13.17 CN13.19 CN13.55 CN13.56 CN13.57 CN13.58 CN15.0 CN15.A2 CN15.A3 CN15.A8 CN15.A10 CN15.A11 CN15.B2 CN15.B3 CN15.B8 CN15.B10 CN15.B11 CN16.17 CN16.18 CN17.17 CN17.18 CN18.17 CN18.18 CN21.0 CN21.A2 CN21.A3 CN21.A8 CN21.A10 CN21.A11 CN21.B2 CN21.B3 CN21.B8 CN21.B10 CN21.B11 CN22.NPTH1 CN22.NPTH2 CN25.0 MIRE1.1 MIRE2.1 MIRE3.1 MIRE4.1 MIRE5.1 MIRE6.1 U8.5 U8.6 U9.5 U9.6 U22.A2 U22.A3 U22.A5 U22.B1 U22.B5 U22.C1 U22.C3 U22.C5 U22.D1 U22.D5 U22.E1 U22.E2 U22.E3 U22.E4 U22.E5 U24.A1 U24.A2 U24.A7 U24.A8 U24.A9 U24.A10 U24.A11 U24.A12 U24.A13 U24.A14 U24.B1 U24.B7 U24.B8 U24.B9 U24.B10 U24.B11 U24.B12 U24.B13 U24.B14 U24.C1 U24.C3 U24.C5 U24.C7 U24.C8 U24.C9 U24.C10 U24.C11 U24.C12 U24.C13 U24.C14 U24.D1 U24.D2 U24.D3 U24.D4 U24.D12 U24.D13 U24.D14 U24.E1 U24.E2 U24.E3 U24.E5 U24.E8 U24.E9 U24.E10 U24.E12 U24.E13 U24.E14 U24.F1 U24.F2 U24.F3 U24.F10 U24.F12 U24.F13 U24.F14 U24.G1 U24.G2 U24.G3 U24.G10 U24.G12 U24.G13 U24.G14 U24.H1 U24.H2 U24.H3 U24.H12 U24.H13 U24.H14 U24.J1 U24.J2 U24.J3 U24.J12 U24.J13 U24.J14 U24.K1 U24.K2 U24.K3 U24.K6 U24.K7 U24.K10 U24.K12 U24.K13 U24.K14 U24.L1 U24.L2 U24.L3 U24.L12 U24.L13 U24.L14 U24.M1 U24.M2 U24.M3 U24.M7 U24.M8 U24.M9 U24.M10 U24.M11 U24.M12 U24.M13 U24.M14 U24.N1 U24.N3 U24.N6 U24.N7 U24.N8 U24.N9 U24.N10 U24.N11 U24.N12 U24.N13 U24.N14 U24.P1 U24.P2 U24.P7 U24.P8 U24.P9 U24.P10 U24.P11 U24.P12 U24.P13 U24.P14 U27.A2 U27.A3 U27.A4 U27.AA4 U27.B1 U27.B2 U27.B3 U27.B4 U27.C1 U27.C2 U27.C3 U27.C10 U27.C12 U27.E10 U27.E11 U27.E13 U27.E15 U27.F11 U27.F13 U27.F14 U27.F15 U27.G12 U27.G14 U27.G16 U27.J7 U27.J18 U27.K3 U27.K17 U27.M3 U27.T18 U27.U16 U27.U18 U27.U19 U27.V6 U27.W4 U28.P9 U28.T7 U29.P9 U29.T7 U30.3 U34.8 U34.9 U34.20 U35.4 U36.A1 U36.A3 U36.A4 U36.A5 U36.A8 U36.A9 U36.A11 U36.A12 U36.A13 U36.B4 U36.B5 U36.B6 U36.B7 U36.B8 U36.B9 U36.B10 U36.B11 U36.B12 U36.B15 U36.C2 U36.C3 U36.C4 U36.C12 U36.C13 U36.C14 U36.C15 U36.D1 U36.D2 U36.D3 U36.D11 U36.D13 U36.D14 U36.E1 U36.E2 U36.E3 U36.E4 U36.E12 U36.E13 U36.E14 U36.E15 U36.F1 U36.F4 U36.F14 U36.G4 U36.G14 U36.G15 U36.H2 U36.H3 U36.H4 U36.H14 U36.J2 U36.J3 U36.J4 U36.K1 U36.K2 U36.K3 U36.K12 U36.K13 U36.K14 U36.K15 U36.L1 U36.L12 U36.L13 U36.L14 U36.L15 U36.M2 U36.M3 U36.M4 U36.M7 U36.M12 U36.M13 U36.M14 U36.M15 U36.N2 U36.N4 U36.N6 U36.N7 U36.N11 U36.N13 U36.N14 U36.N15 U36.P2 U36.P4 U36.P5 U36.P6 U36.P7 U36.P8 U36.P9 U36.P10 U36.P11 U36.P12 U36.P13 U36.P14 U36.P15 U36.R2 U36.R3 U36.R6 U36.R7 U36.R8 U36.R9 U36.R10 U36.R11 U36.R12 U37.5 U42.3 U47.4 U50.7 U50.8

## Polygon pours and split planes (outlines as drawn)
GND on Bottom Layer "GND_L06_P128" (solid, remove dead copper, pour order 128): -1,138 173,138 173,-1 -1,-1
VTT_DDR on Bottom Layer "VTT_DDR_L06_P000" (solid, remove dead copper, pour order 0): 143.05,79.3 143.05,82.2 142.625,82.625 136.725,82.625 136.45,82.9 136.45,84.4 136.8,84.75 143.15,84.75 145.5,82.4 145.5,75.9 144.5,74.9 143.45,74.9 142.825,74.275 142.27,74.275 142.075,74.08 142.075,72.85 140.975,71.75 140.125,71.75 140.075,71.7 140.075,70.775 140.125,70.725 140.35,70.725 140.35,70.03 139.795,70.03 139.795,69.07 140.35,69.07 140.35,64.7 139.922,64.325 127.825,64.325 127.825,66.484 137.7,66.484 137.7,72.625 139.6,72.625 139.6,74.275 140.25,74.925 141,74.925 141,75.425 141.8,76.225 141.375,76.65 141.375,77.6 134.825,77.6 134.8,77.575 134.75,77.625 134.75,79.3
NetC116_2 on Bottom Layer "NETC116_2_L06_P088" (solid, remove dead copper, pour order 88): 11.175,21.525 11.175,28.925 12.55,30.3 17.75,30.3 18.35,29.7 18.35,26.375 16.9,24.925 15.5,24.925 14.325,23.75 14.325,22.35 13.5,21.525
GND on Signal Layer 4 "GND_L05_P127" (solid, remove dead copper, pour order 127): -1,138 173,138 173,-1 -1,-1
VDDGPU on Signal Layer 4 "VDDGPU_L05" (solid, remove dead copper, pour order 90): 96.25,68.65 95.875,69.025 95.4,69.025 95.3,69.125 95.3,69.475 95.325,69.5 95.425,69.6 95.85,69.6 96.175,69.925 96.175,70.5 95.15,71.525 95.15,71.775 94.425,72.5 93.5,72.5 92.95,71.95 92.95,70.822 93.425,70.347 93.425,69.91 92.815,69.3 90.324,69.3 90.324,67.512 90.262,67.45 66.325,67.45 63.75,64.875 63.75,62.94 65.983,60.75 96.25,60.75
5V_VIN on Signal Layer 4 "5V_VIN_L05_P101" (solid, remove dead copper, pour order 101): 53.475,86.925 53.475,91.5 51.025,93.95 51.025,121.075 49,123.1 38.15,123.1 37.15,122.1 37.15,119.25 43.15,113.25 43.15,106.607 40.285,103.742 21.692,103.742 21.3,103.35 21.3,101.725 22.075,100.95 22.075,32.75 12.725,23.4 12.725,7.275 17.775,2.225 151.375,2.225 162.15,13 162.15,59.3 166.9,64.05 166.9,68.3 162.937,72.288 162.937,78.188 158.975,82.15 158.975,86.3 151.15,94.125 151.15,103.775 140.45,114.475 127.823,114.475 126.768,113.42 126.768,111.957 127.925,110.85 133.8,110.85 137.975,106.675 137.975,96.125 144.425,89.675 144.425,83 155.7,71.725 155.7,28.575 150.45,23.325 126.175,23.325 123.975,25.525 121.75,25.525 120.55,24.325 120.55,14.079 118.121,11.65 48.6,11.65 44.625,7.675 38.61,7.675 37.513,8.772 37.513,15.999 36.271,17.24 35.586,17.24 35.053,17.24 33.386,15.573 32.598,15.573 31.275,14.25 31.275,13.317 29.174,11.216 28.759,11.216 28.6,11.375 28.6,17.275 31.325,20 31.325,24.85 31.35,24.875 31.35,37.832 34.293,40.775 56.825,40.775 56.825,49.825 40.825,49.825 38.75,51.9 38.75,58.575 38.75,64.5 40.7,66.45 49.615,66.45 54.315,71.15 54.315,83.8 53.913,84.25 52.575,84.25 51.182,82.857 50.733,82.857 50.418,83.172 50.418,83.868
VDD_DDR on Signal Layer 4 "VDD_DDR" (solid, pour order 4): 94.9,72.801 94.9,72.047 96.325,70.622 96.325,70.28 95.48,69.435 95.48,69.125 95.9,69.125 96.327,68.698 96.326,56.451 95.8,55.925 39.875,55.925 39.125,56.675 39.125,78.625 40.98,80.48 40.98,83.37 39.625,84.725 29.3,84.725 29,84.425 29,60.774 29.5,60.274 31.875,57.95 31.875,51.325 34.15,49.05 113.359,49.05 122.175,57.975 126.1,61.9 126.1,63.05 129.15,66.1 138.525,66.1 141.298,68.873 141.298,77.002 140.825,77.475 138.802,77.475 132.902,83.375 121.95,83.375 119.5,80.925 101.25,80.925 98.075,77.75 98.075,75.976
VDDIO on Signal Layer 4 "VDDIO_L05" (solid, remove dead copper, pour order 91): 56.046,69.304 54.325,71.025 54.325,73.67 54.363,83.8 53.925,84.25 52.575,84.25 51.182,82.857 50.733,82.857 50.418,83.172 50.418,83.901 53.742,87.225 60.475,87.225 62.675,85.025 74.6,73.1 76.2,73.1 77.075,72.225 92.911,72.225 92.911,70.564 93.425,70.05 93.425,69.814 92.911,69.3 90.324,69.3 90.17,69.454 87.82,69.454 87.666,69.3 82.421,69.3 77.53,69.304
VDDCPU on Signal Layer 4 "VDDCPU_L05" (solid, remove dead copper, pour order 3): 66.737,88.162 66.737,91.487 67.175,91.95 68.575,91.95 75.175,85.35 90.358,85.35 97.801,77.907 97.801,75.851 94.575,72.625 93.675,72.625 93.675,75.1 89.593,79.182 75.718,79.182
VDDCORE on Signal Layer 4 "VDDCORE_L05" (solid, remove dead copper, pour order 85): 61.925,92.603 61.925,93.1 62.125,93.3 64.8,93.3 66.55,91.55 66.55,88.475 75.996,79.029 89.321,79.029 93.6,74.75 93.6,72.775 93.05,72.225 77.075,72.225 76.225,73.075 74.775,73.075 61.925,85.925
VDDA1V8_AON on Signal Layer 4 "VDDA1V8_AON_L05_P120" (solid, remove dead copper, pour order 120): 64.712,58.162 74.075,58.162 74.075,60.75 65.983,60.75 63.75,62.983 63.75,64.875 66.325,67.45 90.262,67.45 90.262,69.2 90.008,69.454 87.82,69.454 87.666,69.304 60.875,69.304 60.875,61.998 64.013,58.861
VDD_EMMC on Signal Layer 4 "VDD_EMMC" (solid, pour order 1): 108.175,92.425 105.45,89.7 74.276,89.7 73.839,89.263 73.839,86.861 75.2,85.5 106.775,85.5 112.075,90.8 112.075,91.475 111.125,92.425
VDDIO_SDCARD on Signal Layer 4 "VDDIO_SDCARD_L05_P126" (solid, remove dead copper, pour order 126): 160.725,118.45 161.15,118.025 161.15,117.355 160.62,116.825 156.95,116.825 153.363,113.238 151.087,113.238 147.475,116.85 147.475,118.45
1V5_PCIE on Signal Layer 4 "1V5_PCIE_L05_P119" (solid, remove dead copper, pour order 119): 153.225,63.25 153.225,37.35 149.925,34.05 148.4,34.05 147.875,34.575 147.875,42.763 149.3,44.188 149.3,52.4 148,53.7 148,54.888 149.475,56.363 149.475,62.05 150.675,63.25
3V3_STLK on Signal Layer 4 "3V3_STLK_L05_P094" (solid, remove dead copper, pour order 94): 31.275,14.25 32.567,15.542 32.567,17.357 35.658,20.449 42.299,20.449 44.4,22.55 44.4,27.025 36.45,34.975 36.45,38.115 36.989,38.654 51.261,38.654 51.261,40.775 34.293,40.775 31.325,37.807 31.325,20 28.6,17.275 28.6,11.375 28.759,11.216 29.174,11.216 31.275,13.317
GND on Top Layer "GND_L01_P133" (solid, remove dead copper, pour order 133): -1.25,138 172.75,138 172.75,-1 -1.25,-1
VBUS_STLK on Top Layer "VBUS_STLK" (solid, pour order 131): 32.375,5.5 34.018,5.5 38.825,10.307 38.825,13.1 36.45,13.1 36.4,13.05 36.4,11.775 32.375,7.75
GND on Top Layer "GND_L01_P111" (solid, remove dead copper, pour order 111): 173.162,77.725 173.162,109.59 144.855,109.59 144.855,77.725
I_SENS_VDDGPU_P on Top Layer "I_SENS_VDDGPU_P" (solid, pour order 123): 56.225,78.427 60.135,78.427 62.435,80.727 63.075,80.727 63.075,85.777 62.077,85.777 61.627,85.327 61.325,85.025 61.325,81.927 60.945,81.547 56.225,81.547
3V3 on Top Layer "3V3" (solid, pour order 125): 32.1,71.375 32.275,71.2 38.623,71.2 39.925,72.502 39.925,73.35 32.3,73.35 32.1,73.15
VDDIO on Top Layer "VDDIO" (solid, pour order 124): 50.195,81.597 50.195,83.395 50.73,83.93 50.912,83.93 51.35,83.491 51.35,82.95 50.65,82.25 50.65,81.597
I_SENS_VDDCORE_P on Top Layer "I_SENS_VDDCORE_P" (solid, pour order 122): 54.715,84.027 59.977,84.027 61.55,85.6 61.55,91.752 60.91,91.752 59.85,90.692 59.85,87.952 59.42,87.522 54.705,87.522
I_SENS_VDDCPU_P on Top Layer "I_SENS_VDDCPU_P" (solid, pour order 121): 36.325,90.852 37.623,90.852 38.075,90.4 38.075,87.497 38.9,86.672 41.945,86.672 41.945,84.307 41.95,84.302 37.875,84.302 36.325,85.852
VDDIO on Top Layer "VDDIO" (solid, pour order 118): 69.148,78.727 69.3,78.575 69.3,77.075 69.125,76.9 65.902,76.9 65.075,77.727 64.435,77.727 64.435,78.727
NetL6_1 on Top Layer "NetL13_1" (solid, pour order 114): 52.575,76.69 53.038,76.227 54.3,76.227 54.3,73.927 54.298,73.925 53.001,73.925 53.001,75.549 52.575,75.975
VLED on Top Layer "VLED_L01_P017" (solid, remove dead copper, pour order 17): 38.5,123.45 38.5,127.55 40.355,127.55 40.355,123.45
5V_VIN on Top Layer "5V_VIN" (solid, pour order 113): 41.71,78.447 42.367,78.447 42.55,78.63 42.55,78.29 42.067,77.807 41.71,77.807
5V_STLK on Top Layer "5V_STLK_L01_P016" (solid, remove dead copper, pour order 16): 17.95,20.6 24.75,20.6 30.68,14.67 32.575,14.67 32.575,12.863 27.938,12.863 27.62,12.545 27.62,8.07 28.365,7.325 30.612,7.325 31.075,6.862 31.075,5.5 26.075,5.5 24.4,7.175 24.4,13.225 23.475,14.15 21.05,14.15 17.95,17.25
NetC114_2 on Top Layer "NETC114_2_L01_P108" (solid, remove dead copper, pour order 108): 10.925,30.225 10.925,34.375 9,34.375 9,34.775 9.275,35.05 16.825,35.05 18.7,33.175 18.7,28.775 18,28.075 18,22.165 21.95,22.165 21.95,34.95 19.525,37.375 8.275,37.375 7.225,36.325 7.225,30.225
NetC116_2 on Top Layer "NETC116_2_L01_P107" (solid, remove dead copper, pour order 107): 4.675,14.025 4.675,23.1 5.3,23.725 14.425,23.725 14.425,21.65 11.775,21.65 10.475,20.35 10.475,14.025
VIN_JACK on Top Layer "VIN_JACK_L01_P106" (solid, remove dead copper, pour order 106): 4.675,9.475 18.753,9.475 20.875,11.597 20.875,14.9 19.975,15.8 12.55,15.8 10.5,13.75 4.675,13.75
NetC116_2 on Top Layer "NETC116_2_L01_P051" (solid, remove dead copper, pour order 51): 18.05,28.765 17.63,28.345 17.005,28.345 16.225,29.125 15.475,29.125 15.2,28.85 15.2,27.975 15.125,27.9 14.775,27.9 14.675,28 14.675,30.85 18.05,30.85
NetL8_1 on Top Layer "NETL8_1_L01_P050" (solid, remove dead copper, pour order 50): 12.65,29.975 11.425,29.975 11.2,30.2 11.2,34.575 11.425,34.8 14.325,34.8 14.475,34.65 14.475,28.025 14.35,27.9 13.9,27.9 13.825,27.975 13.825,28.8
GND on Signal Layer 2 "GND_L03_P129" (solid, remove dead copper, pour order 129): -1,138 173,138 173,-1 -1,-1
VBUSc on Signal Layer 2 "VBUSC_L03_P030" (solid, remove dead copper, pour order 30): 164.05,25 158.925,25 157.35,23.425 157.35,11.2 157.725,10.825 158.675,10.825 160.875,13.025 160.875,19.04 162.46,20.625 164.05,20.625
VBUS_STLK on Signal Layer 2 "VBUS_STLK_L03_P031" (solid, remove dead copper, pour order 31): 38.142,13.06 37.528,13.675 36.625,13.675 36.425,13.475 36.425,11.612 37.02,11.017 37.02,11 38.025,11 40.825,8.2 43.775,8.2 43.775,11.9 42.615,13.06 39.265,13.06
3V3_DVDD_RGMII2 on Signal Layer 2 "3V3_DVDD_RGMII2" (solid, remove dead copper, pour order 110): 58.125,29.95 65.1,22.975 67.675,22.975 68.875,24.175 68.875,35.925 68.475,36.325 60.4,36.325 58.125,34.05
3V3_DVDD_RGMII1 on Signal Layer 2 "3V3_DVDD_RGMII1_L03_P093" (solid, remove dead copper, pour order 93): 83.125,29.95 90.1,22.975 92.675,22.975 93.875,24.175 93.875,35.925 93.475,36.325 85.4,36.325 83.125,34.05
VDDIO on Signal Layer 2 "VDDIO_L03_P112" (solid, remove dead copper, pour order 112): 93.888,68.922 99.6,74.634 99.6,78.875 101.925,81.2 101.925,82.325 101.6,82.65 100.7,82.65 97.575,79.525 97.575,75.975 97.2,75.6 94.075,75.6 92.502,77.173 90,77.173 90,70.036 91.113,68.922
3V3_DVDD_RGMII3 on Signal Layer 2 "3V3_DVDD_RGMII3_L03_P103" (solid, remove dead copper, pour order 103): 108.125,29.95 115.1,22.975 117.675,22.975 118.875,24.175 118.875,35.925 118.475,36.325 110.4,36.325 108.125,34.05
GND on Signal Layer 3 "GND_L04_P132" (solid, remove dead copper, pour order 132): -1,138 173,138 173,-1 -1,-1
3V3 on Signal Layer 3 "3V3_L04_P116" (solid, remove dead copper, pour order 116): 39.288,79.413 38.488,79.413 37.275,80.625 37.35,81.35 31.8,86.9 31.8,93.25 34.325,95.775 37.9,95.775 54.3,112.175 64.075,112.175 83.6,92.65 107.1,92.65 109.225,90.525 109.225,89.725 109.61,89.34 110.665,89.34 112.175,90.85 112.175,100.275 123.431,111.531 130.231,111.531 134.588,115.887 134.587,123.888 129.525,128.95 115.075,128.95 114.425,128.3 56.9,128.3 55.3,129.9 11.9,129.9 9.4,127.4 4.775,127.4 4.15,126.775 4.15,126.025 11.7,118.425 11.7,110.775 16.4,106.075 16.4,48.35 45,19.75 149.1,19.75 158.475,10.375 167.7,10.375 167.7,11.795 159.986,19.509 159.986,58.136 162.675,60.825 168.65,60.825 170.55,62.725 170.55,90.81 168.26,93.1 160.3,93.1 159.425,93.975 159.425,109.124 154.954,113.595 150.245,113.595 149.75,113.1 149.75,112.175 150.175,111.75 152.225,111.75 155.71,108.265 155.71,86.01 150.4,80.7 150.4,62.15 145,56.75 47.8,56.75 43.9,60.65 43.9,74.8
1V8 on Signal Layer 3 "1V8_L04_P115" (solid, remove dead copper, pour order 115): 55.375,92.425 56.45,93.5 70.4,93.5 71.925,91.975 78.2,85.7 78.2,69.225 79.125,68.3 83.591,68.3 87.671,72.38 95.62,72.38 97.975,70.025 97.975,66.825 98,66.8 98,65.9 98.7,65.2 99.6,65.2 101.075,66.675 101.075,81.685 102.34,82.95 129.8,82.95 133.3,79.45 140.375,79.45 141.5,80.575 141.5,126.425 138.875,129.05 135.9,129.05 135.425,128.575 135.425,90.053 138.233,87.245 138.233,82.855 137.702,82.323 136.423,82.323 123.28,95.467 52.142,95.467 49.875,93.2 49.875,92.775 50.225,92.425
VTT_DDR on Signal Layer 3 "VTT_DDR" (solid, pour order 2): 52.142,95.575 49.017,92.45 34.698,92.45 34.223,91.975 34.223,89.952 40.075,84.1 40.075,80.2 39.5,79.625 38.8,79.625 37.605,80.82 37.605,81.412 31.925,87.091 31.925,93.075 34.45,95.6 47.375,95.6 50.025,98.25 127.075,98.25 138.125,87.2 138.125,82.9 137.625,82.4 136.5,82.4 123.325,95.575
VDDCPU on Signal Layer 3 "VDDCPU" (solid, pour order 97): 53.875,89.075 52.6,87.8 36.528,87.8 34.3,90.028 34.3,91.898 34.727,92.325 55.25,92.325 55.35,92.325 56.425,93.4 68.95,93.4 68.95,89.075
VDD_SDCARD on Signal Layer 3 "VDD_SDCARD" (solid, pour order 117): 45.715,71.775 47.083,70.407 47.083,68.108 46.577,67.602 45.323,67.602 43.875,69.05 43.875,71.425 44.225,71.775
VDDGPU on Signal Layer 3 "VDDGPU" (solid, pour order 98): 63.947,87.275 65.6,87.275 66.925,85.95 66.925,62.65 66.1,61.825 63.925,61.825 62.375,63.375 62.375,85.703
GND on Signal Layer 1 "GND_L02_P099" (solid, remove dead copper, pour order 99): -1,138 173,138 173,-1 -1,-1

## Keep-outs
Keep-Out Layer:
  lines w0.1: 133.661,133.38 142.561,133.38 142.561,135.53 133.661,135.53 133.661,133.38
